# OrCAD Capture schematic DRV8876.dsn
size A3
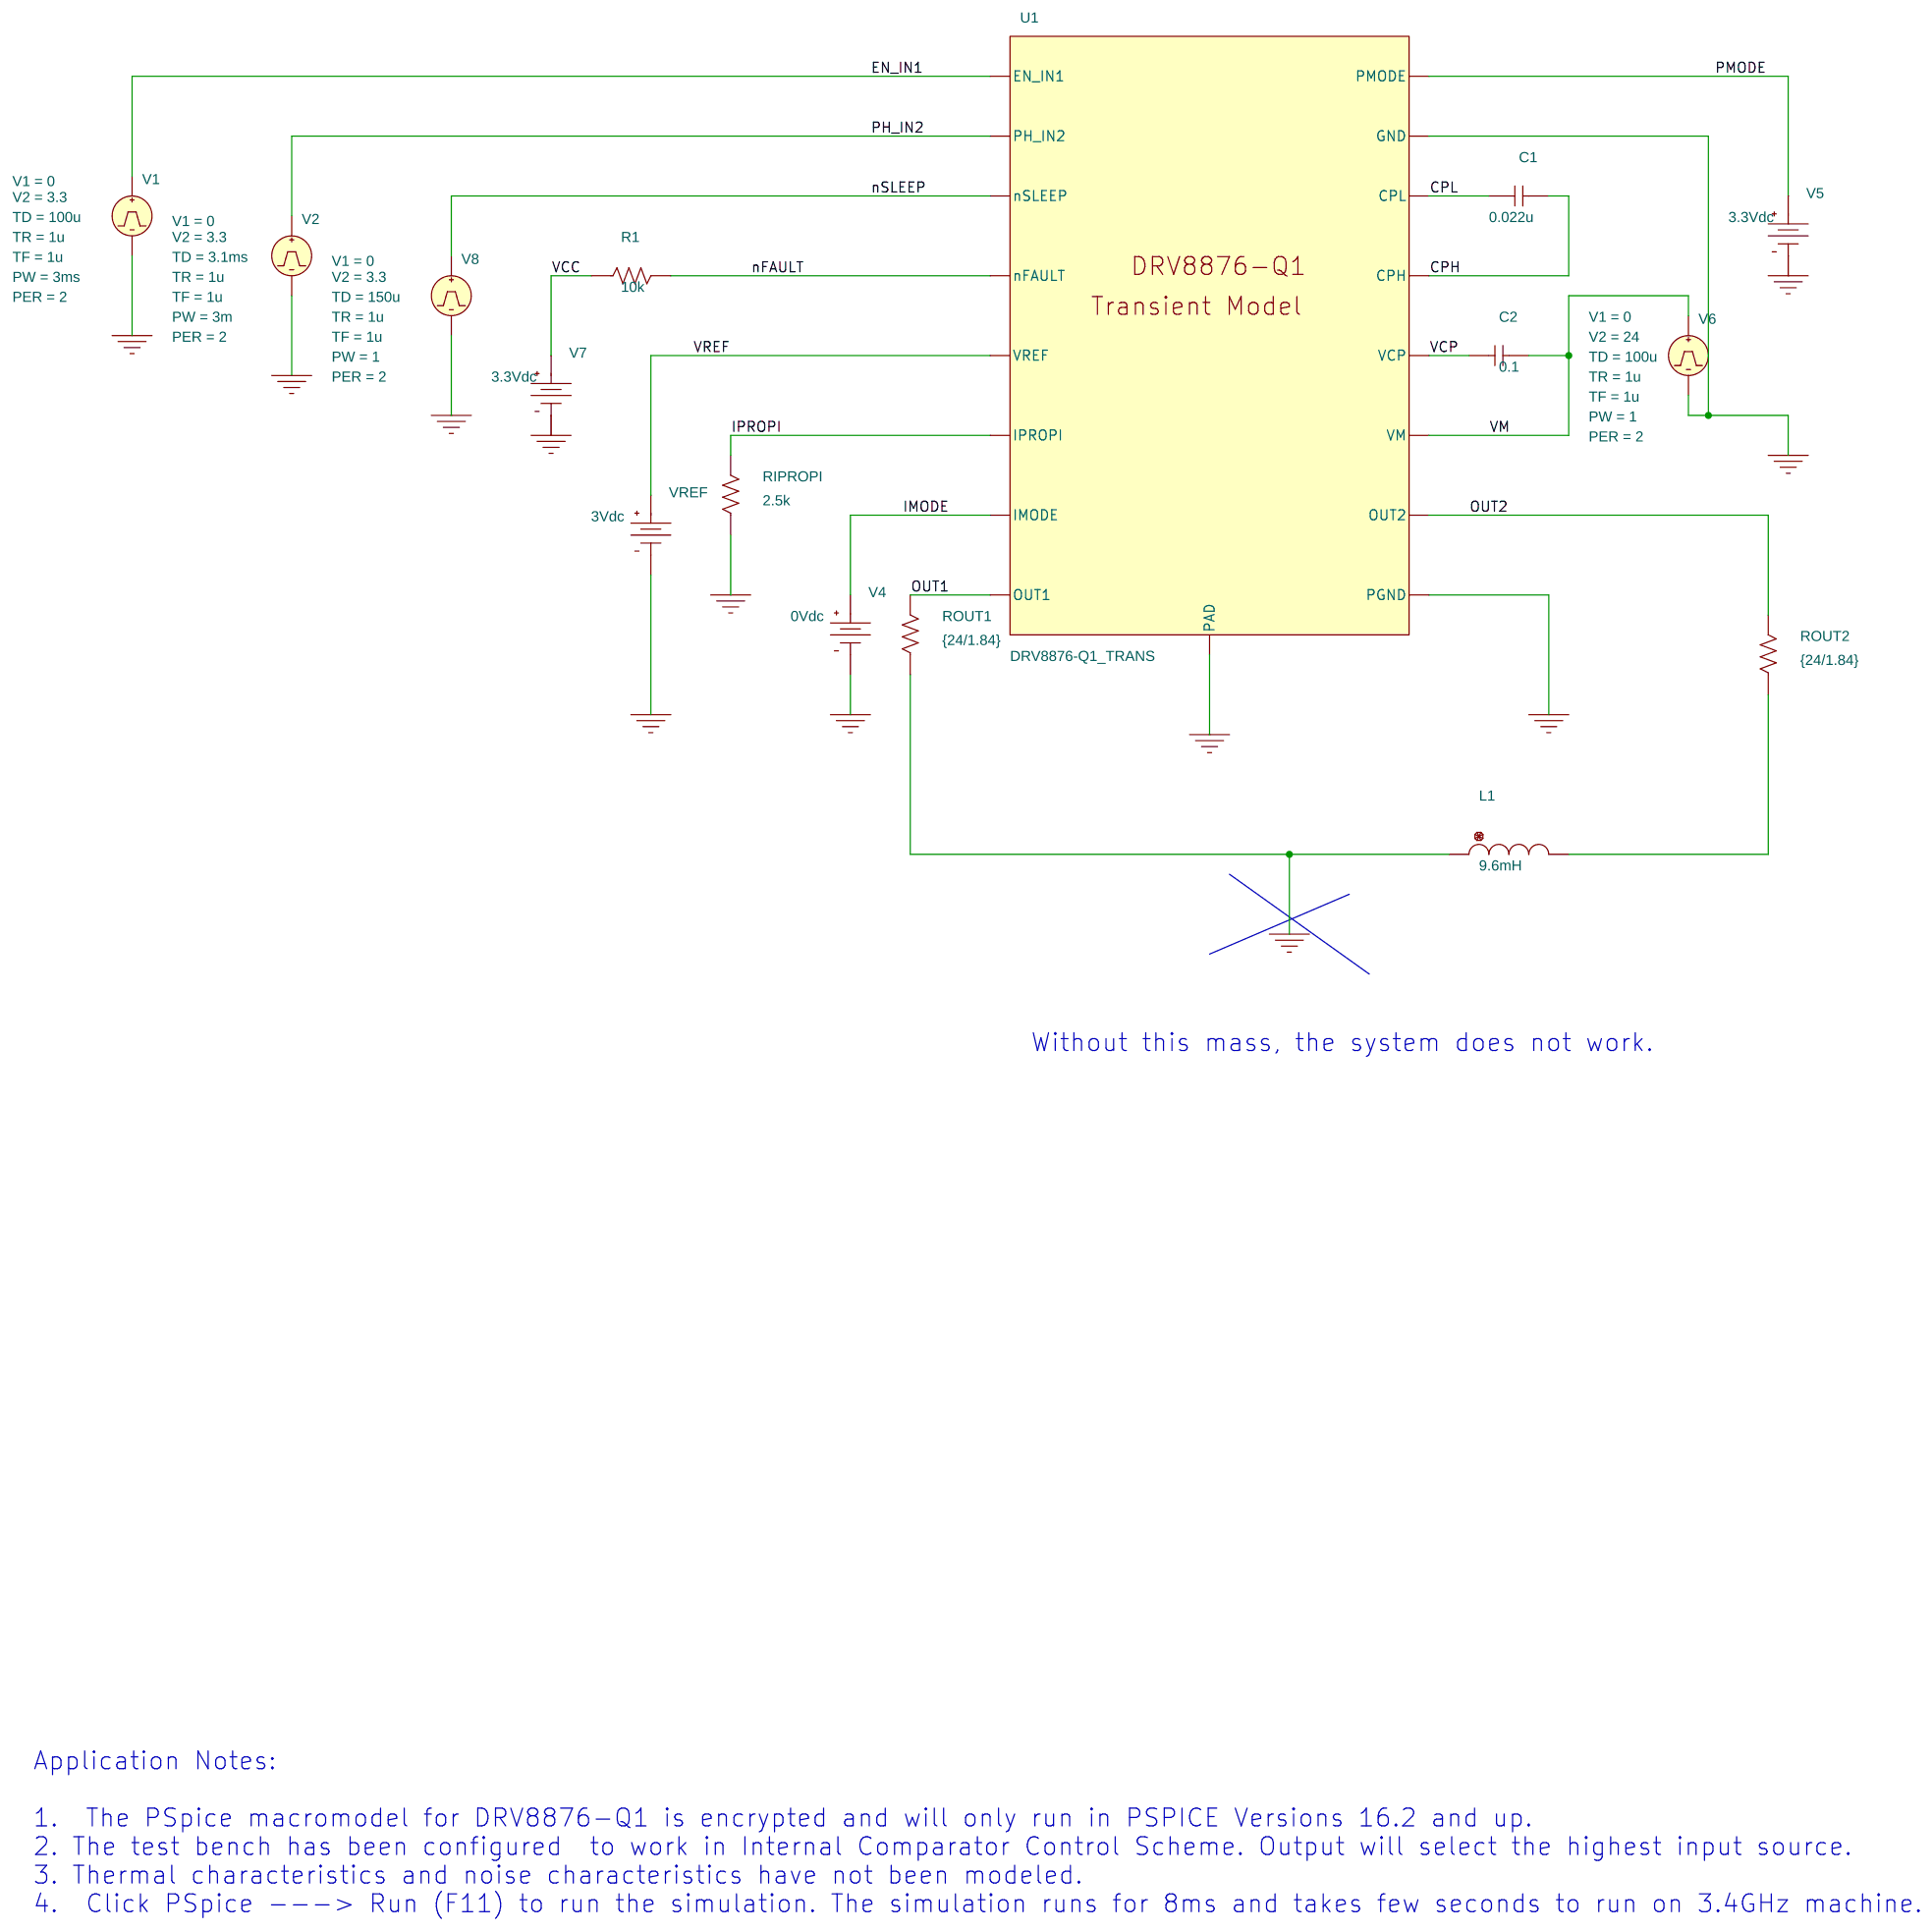
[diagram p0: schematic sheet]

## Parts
C1  0.022u  [RAD/CK05]
C2  0.1  [RAD/CK05]
L1  9.6mH  [DISC350x175LS200x100034]
R1  10k  [AX/RC05]
RIPROPI  2.5k  [AX/RC05]
ROUT1  {24/1.84}  [AX/RC05]
ROUT2  {24/1.84}  [AX/RC05]
U1  DRV8876-Q1_TRANS
V1  VPULSE
V2  VPULSE
V4  VDC
V5  VDC
V6  VPULSE
V7  VDC
V8  VPULSE
VREF  VDC

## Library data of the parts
C1 C2 = C
L1 = L
R1 RIPROPI ROUT1 ROUT2 = R
U1 = DRV8876-Q1_TRANS: PSpiceTemplate: X^@REFDES  %CPH %CPL %EN_IN1 %GND %IMODE %IPROPI %nFAULT %nSLEEP %OUT1 %OUT2 %PGND %PAD %PH_IN2 %PMODE %VCP %VM %VREF @MODEL
V1 = VPULSE: PER: 2; PW: 3ms; TD: 100u; TF: 1u; TR: 1u; V1: 0; V2: 3.3
V2 = VPULSE: PER: 2; PW: 3m; TD: 3.1ms; TF: 1u; TR: 1u; V1: 0; V2: 3.3
V4 = VDC: DC: 0Vdc
V5 V7 = VDC: DC: 3.3Vdc
V6 = VPULSE: PER: 2; PW: 1; TD: 100u; TF: 1u; TR: 1u; V1: 0; V2: 24
V8 = VPULSE: PER: 2; PW: 1; TD: 150u; TF: 1u; TR: 1u; V1: 0; V2: 3.3
VREF = VDC: DC: 3Vdc

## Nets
VCC: R1.1 V7.0(+)
0: L1.1 RIPROPI.1 ROUT1.1 U1.GND U1.PAD U1.PGND V1.2(-) V2.2(-) V4.1(-) V5.1(-) V6.2(-) V7.1(-) V8.2(-) VREF.1(-)
CPH: C1.2 U1.CPH
CPL: C1.1 U1.CPL
EN_IN1: U1.EN_IN1 V1.1(+)
IMODE: U1.IMODE V4.0(+)
IPROPI: RIPROPI.2 U1.IPROPI
nFAULT: R1.2 U1.nFAULT
nSLEEP: U1.nSLEEP V8.1(+)
OUT1: ROUT1.2 U1.OUT1
OUT2: ROUT2.2 U1.OUT2
PH_IN2: U1.PH_IN2 V2.1(+)
PMODE: U1.PMODE V5.0(+)
VCP: C2.1 U1.VCP
VM: C2.2 U1.VM V6.1(+)
VREF: U1.VREF VREF.0(+)
N345276: L1.2 ROUT2.1

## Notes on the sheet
- Without this mass, the system does not work.
- Application Notes:
  1.  The PSpice macromodel for DRV8876-Q1 is encrypted and will only run in PSPICE Versions 16.2 and up.
  2. The test bench has been configured  to work in Internal Comparator Control Scheme. Output will select the highest input source.
  3. Thermal characteristics and noise characteristics have not been modeled.
  4.  Click PSpice ---> Run (F11) to run the simulation. The simulation runs for 8ms and takes few seconds to run on 3.4GHz machine.
